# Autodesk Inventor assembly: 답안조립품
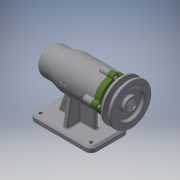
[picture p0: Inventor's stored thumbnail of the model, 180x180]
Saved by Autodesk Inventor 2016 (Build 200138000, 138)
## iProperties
Created: 2019-07
Part Number: 답안조립품
Material: 일반
Document SubType Name: Assembly
Designer: 605-01
Author: 605-01
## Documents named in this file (12)
- C:\Users\605-01\Desktop\490704V1018\답안조립품.iam
- C:\Users\605-01\Desktop\490704V1018\본체.ipt
- C:\Users\605-01\Desktop\490704V1018\V벨트풀리.ipt
- C:\Users\605-01\Desktop\490704V1018\멈춤나사 M3.ipt
- C:\Users\605-01\Desktop\490704V1018\베어링 6004.ipt
- C:\Users\605-01\Desktop\490704V1018\베어링 51202.ipt
- C:\Users\605-01\Desktop\490704V1018\볼트 M4.ipt
- C:\Users\605-01\Desktop\490704V1018\어댑터슬리브.ipt
- C:\Users\605-01\Desktop\490704V1018\오일 실.ipt
- C:\Users\605-01\Desktop\490704V1018\축.ipt
- C:\Users\605-01\Desktop\490704V1018\커버.ipt
- C:\Users\605-01\Desktop\490704V1018\키 5 x 5 x 16.ipt
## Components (1 placed, 1 different names)
1. V벨트풀리:1
